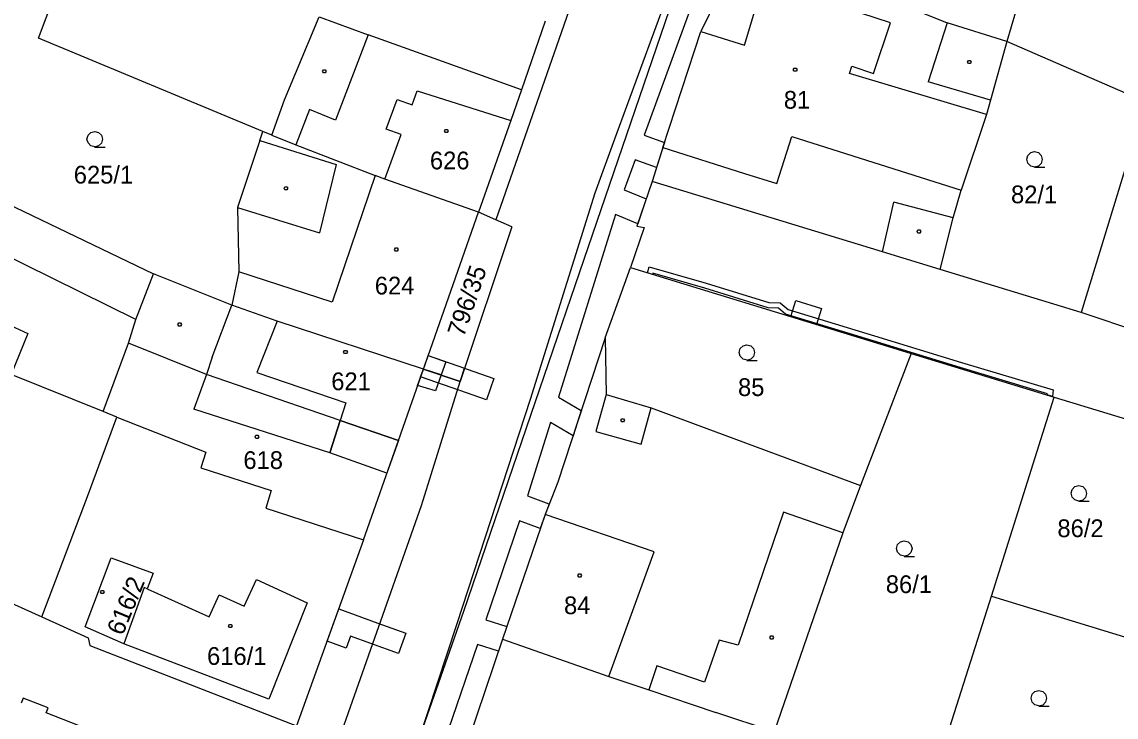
# Model space of a CAD drawing. Extents: x -759060 to -757386, y -1172273 to -1170948.
# Drawn here: x -758112.4 to -758007.6, y -1171497.5 to -1171430.9 of the extents above; entities that cross this region are included whole.
import ezdxf

# ---------------------------------------------------------------- set-up
doc = ezdxf.new("R2010")
doc.units = 0
for name, color, linetype in [('Vrstva 1', 7, 'Continuous'), ('Vrstva 12', 7, 'Continuous'), ('Vrstva 13', 7, 'Continuous'), ('Vrstva 2', 7, 'Continuous'), ('Vrstva 3', 7, 'Continuous'), ('Vrstva 4', 7, 'Continuous'), ('Vrstva 5', 7, 'Continuous')]:
    doc.layers.add(name, color=color, linetype=linetype)

msp = doc.modelspace()

# ---------------------------------------------------------------- linework, layer by layer
at = {"layer": 'Vrstva 1'}
for p, q in [((-758110.83, -1171432.43), (-758104.44, -1171415.39)), ((-758046.35, -1171417.81), (-758059.41, -1171456.07)), ((-758043.49, -1171423.81), (-758047.38, -1171431.8)), ((-758036.5, -1171425.83), (-758023.76, -1171430.96)), ((-758016.01, -1171425.87), (-758018.06, -1171432.75)), ((-758059.12, -1171427.2), (-758067.02, -1171449.84)), ((-758087.25, -1171438.35), (-758083.93, -1171430.4)), ((-758083.93, -1171430.4), (-758079.26, -1171432.11)), ((-758062.28, -1171430.8), (-758064.57, -1171437.39)), ((-758018.06, -1171432.75), (-758023.76, -1171430.96)), ((-758089.34, -1171441.38), (-758110.83, -1171432.43)), ((-758064.57, -1171437.39), (-758079.26, -1171432.11)), ((-758051.01, -1171442.93), (-758047.38, -1171431.8)), ((-758018.06, -1171432.75), (-758019.63, -1171438.39)), ((-758004.78, -1171438.56), (-758018.06, -1171432.75)), ((-758064.57, -1171437.39), (-758065.59, -1171440.32)), ((-758088.48, -1171441.74), (-758087.25, -1171438.35)), ((-758019.63, -1171438.39), (-758020.01, -1171439.77)), ((-758004.78, -1171438.56), (-758010.94, -1171458.73)), ((-758020.01, -1171439.77), (-758022.43, -1171447.01)), ((-758065.59, -1171440.32), (-758068.67, -1171449.1)), ((-758089.63, -1171442.25), (-758089.34, -1171441.38)), ((-758088.48, -1171441.74), (-758089.34, -1171441.38)), ((-758088.48, -1171441.74), (-758086.18, -1171442.66)), ((-758089.63, -1171442.25), (-758091.78, -1171448.65)), ((-758086.18, -1171442.66), (-758078.58, -1171445.61)), ((-758051.01, -1171442.93), (-758052.05, -1171446.17)), ((-758077.64, -1171445.94), (-758078.58, -1171445.61)), ((-758068.67, -1171449.1), (-758077.64, -1171445.94)), ((-758116.29, -1171447.1), (-758099.8, -1171455.02)), ((-758052.05, -1171446.17), (-758053.5, -1171450.45)), ((-758029.96, -1171452.92), (-758052.05, -1171446.17)), ((-758023.21, -1171449.66), (-758022.43, -1171447.01)), ((-758091.78, -1171448.65), (-758091.65, -1171454.84)), ((-758073.95, -1171464.14), (-758068.67, -1171449.1)), ((-758067.02, -1171449.84), (-758068.67, -1171449.1)), ((-758065.49, -1171450.52), (-758067.02, -1171449.84)), ((-758024.46, -1171454.6), (-758023.21, -1171449.66)), ((-758065.49, -1171450.52), (-758070.43, -1171465.33)), ((-758052.81, -1171450.57), (-758054.12, -1171454.42)), ((-758053.5, -1171450.45), (-758052.81, -1171450.57)), ((-758101.51, -1171459.4), (-758117.63, -1171451.45)), ((-758024.46, -1171454.6), (-758029.96, -1171452.92)), ((-758056.54, -1171461.15), (-758054.12, -1171454.42)), ((-758054.12, -1171454.42), (-758028.57, -1171462.23)), ((-758092.32, -1171458.03), (-758099.8, -1171455.02)), ((-758091.65, -1171454.84), (-758092.32, -1171458.03)), ((-758010.94, -1171458.73), (-758024.46, -1171454.6)), ((-758059.41, -1171456.07), (-758070.1, -1171487.39)), ((-758087.98, -1171459.55), (-758092.32, -1171458.03)), ((-757992.49, -1171464.9), (-758010.94, -1171458.73)), ((-758102.21, -1171461.65), (-758101.51, -1171459.4)), ((-758073.95, -1171464.14), (-758087.98, -1171459.55)), ((-758094.74, -1171464.66), (-758102.21, -1171461.65)), ((-758056.54, -1171461.15), (-758061.08, -1171474.99)), ((-758056.54, -1171461.15), (-758056.45, -1171466.59)), ((-758027.23, -1171462.64), (-758032.08, -1171475.31)), ((-758028.57, -1171462.23), (-758027.23, -1171462.64)), ((-758027.23, -1171462.64), (-758013.51, -1171466.83)), ((-758104.65, -1171468.2), (-758113.46, -1171464.68)), ((-758081.93, -1171469.06), (-758094.74, -1171464.66)), ((-758076.35, -1171470.98), (-758073.95, -1171464.14)), ((-758073.95, -1171464.14), (-758070.43, -1171465.33)), ((-758074.15, -1171477.21), (-758070.43, -1171465.33)), ((-758056.45, -1171466.59), (-758052.12, -1171467.85)), ((-758019.54, -1171485.89), (-758013.51, -1171466.83)), ((-758013.51, -1171466.83), (-757981.97, -1171476.47)), ((-758052.12, -1171467.85), (-758032.08, -1171475.31)), ((-758106.13, -1171476.36), (-758103.32, -1171468.77)), ((-758103.32, -1171468.77), (-758104.65, -1171468.2)), ((-758103.32, -1171468.77), (-758094.81, -1171472.1)), ((-758076.35, -1171470.98), (-758081.93, -1171469.06)), ((-758079.69, -1171480.51), (-758076.35, -1171470.98)), ((-758094.81, -1171472.1), (-758095.29, -1171473.61)), ((-758095.29, -1171473.61), (-758088.54, -1171475.77)), ((-758061.08, -1171474.99), (-758062.3, -1171478.07)), ((-758032.08, -1171475.31), (-758033.78, -1171479.83)), ((-758110.52, -1171487.88), (-758106.13, -1171476.36)), ((-758088.54, -1171475.77), (-758089.05, -1171477.46)), ((-758089.05, -1171477.46), (-758079.69, -1171480.51)), ((-758084.78, -1171507.41), (-758074.15, -1171477.21)), ((-758062.3, -1171478.07), (-758066.38, -1171490.03)), ((-758079.69, -1171480.51), (-758086.11, -1171498.34)), ((-758033.78, -1171479.83), (-758040.36, -1171498.92)), ((-758106.36, -1171488.85), (-758103.86, -1171482.22)), ((-758103.86, -1171482.22), (-758099.86, -1171483.71)), ((-758099.86, -1171483.71), (-758100.41, -1171485.2)), ((-758115.54, -1171485.61), (-758110.52, -1171487.88)), ((-758100.71, -1171485.09), (-758102.66, -1171490.46)), ((-758100.41, -1171485.2), (-758100.71, -1171485.09)), ((-758025.27, -1171504), (-758019.54, -1171485.89)), ((-758019.54, -1171485.89), (-757986.07, -1171496.14)), ((-758110.52, -1171487.88), (-758106.09, -1171489.91)), ((-758070.1, -1171487.39), (-758079.12, -1171512.99)), ((-758102.66, -1171490.46), (-758106.36, -1171488.85)), ((-758106.09, -1171489.91), (-758105.93, -1171490.64)), ((-758066.38, -1171490.03), (-758075.53, -1171517.08)), ((-758066.38, -1171490.03), (-758056.18, -1171493.59)), ((-758105.93, -1171490.64), (-758086.11, -1171498.34)), ((-758056.18, -1171493.59), (-758052.37, -1171494.89)), ((-758052.37, -1171494.89), (-758045.94, -1171497.05)), ((-758040.36, -1171498.92), (-758045.94, -1171497.05))]:
    msp.add_line(p, q, dxfattribs=at)
at = {"layer": 'Vrstva 12'}
for p, q in [((-758043.18, -1171433.12), (-758041.4, -1171427.09)), ((-758029.2, -1171430.96), (-758032.03, -1171430.06)), ((-758030.83, -1171435.82), (-758029.2, -1171430.96)), ((-758051.01, -1171442.93), (-758047.38, -1171431.8)), ((-758047.38, -1171431.8), (-758043.18, -1171433.12)), ((-758033.12, -1171435.84), (-758032.91, -1171435.12)), ((-758032.91, -1171435.12), (-758030.83, -1171435.82)), ((-758020.01, -1171439.77), (-758033.12, -1171435.84)), ((-758075.04, -1171438.83), (-758074.56, -1171437.5)), ((-758074.56, -1171437.5), (-758065.59, -1171440.32)), ((-758077.51, -1171441.16), (-758076.47, -1171438.31)), ((-758076.47, -1171438.31), (-758075.04, -1171438.83)), ((-758020.01, -1171439.77), (-758022.43, -1171447.01)), ((-758065.59, -1171440.32), (-758068.67, -1171449.1)), ((-758077.64, -1171445.94), (-758076.09, -1171441.68)), ((-758076.09, -1171441.68), (-758077.51, -1171441.16)), ((-758040.1, -1171446.38), (-758038.66, -1171441.86)), ((-758038.66, -1171441.86), (-758022.43, -1171447.01)), ((-758051.01, -1171442.93), (-758043.19, -1171445.4)), ((-758078.58, -1171445.61), (-758082.71, -1171457.73)), ((-758077.64, -1171445.94), (-758078.58, -1171445.61)), ((-758068.67, -1171449.1), (-758077.64, -1171445.94)), ((-758068.67, -1171449.1), (-758077.64, -1171445.94)), ((-758043.19, -1171445.4), (-758040.1, -1171446.38)), ((-758073.95, -1171464.14), (-758068.67, -1171449.1)), ((-758091.65, -1171454.84), (-758092.32, -1171458.03)), ((-758082.71, -1171457.73), (-758091.65, -1171454.84)), ((-758087.98, -1171459.55), (-758092.32, -1171458.03)), ((-758087.98, -1171459.55), (-758089.92, -1171464.48)), ((-758073.95, -1171464.14), (-758087.98, -1171459.55)), ((-758073.95, -1171464.14), (-758087.98, -1171459.55)), ((-758104.65, -1171468.2), (-758102.21, -1171461.65)), ((-758094.74, -1171464.66), (-758102.21, -1171461.65)), ((-758094.74, -1171464.66), (-758095.96, -1171467.98)), ((-758089.92, -1171464.48), (-758081.4, -1171467.39)), ((-758076.35, -1171470.98), (-758073.95, -1171464.14)), ((-758082.93, -1171472.16), (-758095.96, -1171467.98)), ((-758081.4, -1171467.39), (-758081.93, -1171469.06)), ((-758103.32, -1171468.77), (-758104.65, -1171468.2)), ((-758103.32, -1171468.77), (-758094.81, -1171472.1)), ((-758081.93, -1171469.06), (-758082.93, -1171472.16)), ((-758076.35, -1171470.98), (-758081.93, -1171469.06)), ((-758076.35, -1171470.98), (-758081.93, -1171469.06)), ((-758079.69, -1171480.51), (-758076.35, -1171470.98)), ((-758094.81, -1171472.1), (-758095.29, -1171473.61)), ((-758095.29, -1171473.61), (-758088.54, -1171475.77)), ((-758088.54, -1171475.77), (-758089.05, -1171477.46)), ((-758089.05, -1171477.46), (-758079.69, -1171480.51)), ((-758062.3, -1171478.07), (-758066.38, -1171490.03)), ((-758051.85, -1171481.65), (-758062.3, -1171478.07)), ((-758056.18, -1171493.59), (-758051.85, -1171481.65)), ((-758106.36, -1171488.85), (-758103.86, -1171482.22)), ((-758103.86, -1171482.22), (-758099.86, -1171483.71)), ((-758099.86, -1171483.71), (-758100.41, -1171485.2)), ((-758091.13, -1171486.88), (-758089.95, -1171484.32)), ((-758089.95, -1171484.32), (-758085.1, -1171486.56)), ((-758100.71, -1171485.09), (-758102.66, -1171490.46)), ((-758100.71, -1171485.09), (-758102.66, -1171490.46)), ((-758100.41, -1171485.2), (-758100.71, -1171485.09)), ((-758100.41, -1171485.2), (-758100.71, -1171485.09)), ((-758100.41, -1171485.2), (-758094.49, -1171487.89)), ((-758094.49, -1171487.89), (-758093.52, -1171485.78)), ((-758093.52, -1171485.78), (-758091.13, -1171486.88)), ((-758085.1, -1171486.56), (-758088.77, -1171495.79)), ((-758102.66, -1171490.46), (-758106.36, -1171488.85)), ((-758066.38, -1171490.03), (-758056.18, -1171493.59)), ((-758088.77, -1171495.79), (-758102.66, -1171490.46)), ((-758112.3, -1171495.68), (-758112.48, -1171496.15)), ((-758109.92, -1171496.61), (-758112.3, -1171495.68)), ((-758110.11, -1171497.08), (-758109.92, -1171496.61)), ((-758107, -1171498.3), (-758110.11, -1171497.08))]:
    msp.add_line(p, q, dxfattribs=at)
at = {"layer": 'Vrstva 13'}
for p, q in [((-758055.6, -1171442.07), (-758047.66, -1171420.43)), ((-758045.73, -1171422.42), (-758052.82, -1171441.75)), ((-758052.82, -1171441.75), (-758050.85, -1171442.45)), ((-758057.5, -1171447.26), (-758055.6, -1171442.07)), ((-758050.85, -1171442.45), (-758051.62, -1171444.83)), ((-758053.68, -1171444.09), (-758054.73, -1171446.97)), ((-758051.62, -1171444.83), (-758053.68, -1171444.09)), ((-758054.73, -1171446.97), (-758052.62, -1171447.84)), ((-758063.69, -1171467.03), (-758057.5, -1171447.26)), ((-758052.62, -1171447.84), (-758053.42, -1171450.22)), ((-758055.54, -1171449.34), (-758061.01, -1171466.83)), ((-758053.42, -1171450.22), (-758055.54, -1171449.34)), ((-758052.48, -1171454.92), (-758052.33, -1171454.34)), ((-758052.33, -1171454.34), (-758046.86, -1171455.91)), ((-758052, -1171455.07), (-758052.48, -1171454.92)), ((-758051.97, -1171454.96), (-758052, -1171455.07)), ((-758047, -1171456.39), (-758051.97, -1171454.96)), ((-758040.94, -1171458.28), (-758047, -1171456.39)), ((-758046.86, -1171455.91), (-758040.86, -1171457.78)), ((-758038.74, -1171459.12), (-758038.27, -1171457.58)), ((-758038.27, -1171457.58), (-758035.82, -1171458.33)), ((-758039.94, -1171458.31), (-758040.94, -1171458.28)), ((-758040.86, -1171457.78), (-758039.76, -1171457.81)), ((-758039.26, -1171458.88), (-758039.94, -1171458.31)), ((-758039.76, -1171457.81), (-758039.02, -1171458.44)), ((-758039.02, -1171458.44), (-758030.74, -1171460.96)), ((-758035.82, -1171458.33), (-758036.29, -1171459.87)), ((-758030.88, -1171461.44), (-758039.26, -1171458.88)), ((-758036.29, -1171459.87), (-758038.74, -1171459.12)), ((-758022.53, -1171464), (-758030.88, -1171461.44)), ((-758030.74, -1171460.96), (-758022.39, -1171463.52)), ((-758073.95, -1171464.14), (-758073.5, -1171462.85)), ((-758073.95, -1171464.14), (-758073.5, -1171462.85)), ((-758073.5, -1171462.85), (-758070.01, -1171464.07)), ((-758073.5, -1171462.85), (-758071.8, -1171463.44)), ((-758071.8, -1171463.44), (-758072.26, -1171464.71)), ((-758022.39, -1171463.52), (-758013.62, -1171466.15)), ((-758074.51, -1171465.73), (-758073.95, -1171464.14)), ((-758074.22, -1171464.9), (-758073.95, -1171464.14)), ((-758070.46, -1171466.21), (-758074.22, -1171464.9)), ((-758070.43, -1171465.33), (-758073.95, -1171464.14)), ((-758073.95, -1171464.14), (-758070.43, -1171465.33)), ((-758072.26, -1171464.71), (-758073.95, -1171464.14)), ((-758073.95, -1171464.14), (-758072.26, -1171464.71)), ((-758072.26, -1171464.71), (-758072.8, -1171466.24)), ((-758070.01, -1171464.07), (-758070.43, -1171465.33)), ((-758070.43, -1171465.33), (-758070.01, -1171464.07)), ((-758070.01, -1171464.07), (-758069.75, -1171464.17)), ((-758069.75, -1171464.17), (-758067.2, -1171465.06)), ((-758014.16, -1171466.51), (-758022.53, -1171464)), ((-758072.8, -1171466.24), (-758074.51, -1171465.73)), ((-758067.2, -1171465.06), (-758067.92, -1171467.1)), ((-758070.73, -1171488.51), (-758063.69, -1171467.03)), ((-758067.92, -1171467.1), (-758070.46, -1171466.21)), ((-758061.01, -1171466.83), (-758058.83, -1171468.12)), ((-758014.18, -1171466.63), (-758014.16, -1171466.51)), ((-758013.69, -1171466.78), (-758014.18, -1171466.63)), ((-758013.62, -1171466.15), (-758013.69, -1171466.78)), ((-758058.83, -1171468.12), (-758059.62, -1171470.55)), ((-758082.93, -1171472.16), (-758081.93, -1171469.06)), ((-758081.93, -1171469.06), (-758076.35, -1171470.98)), ((-758061.78, -1171469.28), (-758063.97, -1171476.3)), ((-758059.62, -1171470.55), (-758061.78, -1171469.28)), ((-758076.35, -1171470.98), (-758077.45, -1171474.12)), ((-758077.45, -1171474.12), (-758082.93, -1171472.16)), ((-758063.97, -1171476.3), (-758061.94, -1171477.07)), ((-758061.91, -1171477.08), (-758062.3, -1171478.07)), ((-758061.94, -1171477.07), (-758061.91, -1171477.08)), ((-758062.3, -1171478.07), (-758062.76, -1171479.43)), ((-758064.75, -1171478.68), (-758067.97, -1171488.16)), ((-758062.76, -1171479.43), (-758064.75, -1171478.68)), ((-758083.19, -1171490.22), (-758082.07, -1171487.13)), ((-758082.07, -1171487.13), (-758078.31, -1171488.48)), ((-758084.83, -1171531.29), (-758070.73, -1171488.51)), ((-758078.31, -1171488.48), (-758075.65, -1171489.44)), ((-758067.97, -1171488.16), (-758065.95, -1171488.82)), ((-758065.95, -1171488.82), (-758066.38, -1171490.03)), ((-758080.94, -1171489.73), (-758081.35, -1171490.88)), ((-758079, -1171490.43), (-758080.94, -1171489.73)), ((-758075.65, -1171489.44), (-758076.35, -1171491.39)), ((-758066.38, -1171490.03), (-758066.75, -1171491.18)), ((-758081.35, -1171490.88), (-758083.19, -1171490.22)), ((-758076.35, -1171491.39), (-758079, -1171490.43)), ((-758068.78, -1171490.53), (-758072.87, -1171502.5)), ((-758066.75, -1171491.18), (-758068.78, -1171490.53))]:
    msp.add_line(p, q, dxfattribs=at)
at = {"layer": 'Vrstva 3'}
for points in [[(-758105.44, -1171442.85), (-758105.82, -1171442.75), (-758106.09, -1171442.48), (-758106.19, -1171442.11), (-758106.09, -1171441.74), (-758105.82, -1171441.47), (-758105.45, -1171441.37), (-758105.08, -1171441.47), (-758104.81, -1171441.74), (-758104.71, -1171442.12), (-758104.81, -1171442.5), (-758105.08, -1171442.77), (-758105.46, -1171442.87), (-758104.46, -1171442.87)], [(-758015.39, -1171444.79), (-758015.77, -1171444.69), (-758016.04, -1171444.42), (-758016.14, -1171444.05), (-758016.04, -1171443.68), (-758015.77, -1171443.41), (-758015.4, -1171443.31), (-758015.03, -1171443.41), (-758014.76, -1171443.68), (-758014.66, -1171444.06), (-758014.76, -1171444.44), (-758015.03, -1171444.71), (-758015.41, -1171444.81), (-758014.41, -1171444.81)], [(-758042.95, -1171463.29), (-758043.33, -1171463.19), (-758043.6, -1171462.92), (-758043.7, -1171462.55), (-758043.6, -1171462.18), (-758043.33, -1171461.91), (-758042.96, -1171461.81), (-758042.59, -1171461.91), (-758042.32, -1171462.18), (-758042.22, -1171462.56), (-758042.32, -1171462.94), (-758042.59, -1171463.21), (-758042.97, -1171463.31), (-758041.97, -1171463.31)], [(-758011.15, -1171476.79), (-758011.53, -1171476.69), (-758011.8, -1171476.42), (-758011.9, -1171476.05), (-758011.8, -1171475.68), (-758011.53, -1171475.41), (-758011.16, -1171475.31), (-758010.79, -1171475.41), (-758010.52, -1171475.68), (-758010.42, -1171476.06), (-758010.52, -1171476.44), (-758010.79, -1171476.71), (-758011.17, -1171476.81), (-758010.17, -1171476.81)], [(-758027.87, -1171482.07), (-758028.25, -1171481.97), (-758028.52, -1171481.7), (-758028.62, -1171481.33), (-758028.52, -1171480.96), (-758028.25, -1171480.69), (-758027.88, -1171480.59), (-758027.51, -1171480.69), (-758027.24, -1171480.96), (-758027.14, -1171481.34), (-758027.24, -1171481.72), (-758027.51, -1171481.99), (-758027.89, -1171482.09), (-758026.89, -1171482.09)], [(-758014.98, -1171496.42), (-758015.36, -1171496.32), (-758015.63, -1171496.05), (-758015.73, -1171495.68), (-758015.63, -1171495.31), (-758015.36, -1171495.04), (-758014.99, -1171494.94), (-758014.62, -1171495.04), (-758014.35, -1171495.31), (-758014.25, -1171495.69), (-758014.35, -1171496.07), (-758014.62, -1171496.34), (-758015, -1171496.44), (-758014, -1171496.44)]]:
    msp.add_lwpolyline(points, dxfattribs=at)
at = {"layer": 'Vrstva 4'}
for p, q in [((-758043.18, -1171433.12), (-758041.4, -1171427.09)), ((-758029.2, -1171430.96), (-758032.03, -1171430.06)), ((-758030.83, -1171435.82), (-758029.2, -1171430.96)), ((-758023.76, -1171430.96), (-758025.61, -1171436.63)), ((-758079.26, -1171432.11), (-758082.38, -1171440.29)), ((-758047.38, -1171431.8), (-758043.18, -1171433.12)), ((-758033.12, -1171435.84), (-758032.91, -1171435.12)), ((-758032.91, -1171435.12), (-758030.83, -1171435.82)), ((-758020.01, -1171439.77), (-758033.12, -1171435.84)), ((-758019.63, -1171438.39), (-758025.61, -1171436.63)), ((-758075.04, -1171438.83), (-758074.56, -1171437.5)), ((-758074.56, -1171437.5), (-758065.59, -1171440.32)), ((-758077.51, -1171441.16), (-758076.47, -1171438.31)), ((-758076.47, -1171438.31), (-758075.04, -1171438.83)), ((-758084.88, -1171439.28), (-758086.18, -1171442.66)), ((-758082.38, -1171440.29), (-758084.88, -1171439.28)), ((-758077.64, -1171445.94), (-758076.09, -1171441.68)), ((-758076.09, -1171441.68), (-758077.51, -1171441.16)), ((-758040.1, -1171446.38), (-758038.66, -1171441.86)), ((-758038.66, -1171441.86), (-758022.43, -1171447.01)), ((-758089.63, -1171442.25), (-758082.31, -1171444.54)), ((-758051.01, -1171442.93), (-758043.19, -1171445.4)), ((-758082.31, -1171444.54), (-758083.91, -1171451.09)), ((-758078.58, -1171445.61), (-758082.71, -1171457.73)), ((-758043.19, -1171445.4), (-758040.1, -1171446.38)), ((-758029.96, -1171452.92), (-758028.89, -1171448.14)), ((-758023.21, -1171449.66), (-758028.89, -1171448.14)), ((-758091.78, -1171448.65), (-758083.91, -1171451.09)), ((-758101.51, -1171459.4), (-758099.8, -1171455.02)), ((-758082.71, -1171457.73), (-758091.65, -1171454.84)), ((-758094.18, -1171463.02), (-758092.32, -1171458.03)), ((-758115.53, -1171459.03), (-758111.86, -1171460.75)), ((-758087.98, -1171459.55), (-758089.92, -1171464.48)), ((-758111.86, -1171460.75), (-758113.46, -1171464.68)), ((-758104.65, -1171468.2), (-758102.21, -1171461.65)), ((-758094.18, -1171463.02), (-758094.74, -1171464.66)), ((-758094.74, -1171464.66), (-758095.96, -1171467.98)), ((-758089.92, -1171464.48), (-758081.4, -1171467.39)), ((-758056.45, -1171466.59), (-758057.45, -1171470.13)), ((-758082.93, -1171472.16), (-758095.96, -1171467.98)), ((-758081.4, -1171467.39), (-758081.93, -1171469.06)), ((-758053.09, -1171471.35), (-758052.12, -1171467.85)), ((-758081.93, -1171469.06), (-758082.93, -1171472.16)), ((-758057.45, -1171470.13), (-758053.09, -1171471.35)), ((-758051.85, -1171481.65), (-758062.3, -1171478.07)), ((-758039.45, -1171477.87), (-758043.79, -1171490.61)), ((-758033.78, -1171479.83), (-758039.45, -1171477.87)), ((-758056.18, -1171493.59), (-758051.85, -1171481.65)), ((-758091.13, -1171486.88), (-758089.95, -1171484.32)), ((-758089.95, -1171484.32), (-758085.1, -1171486.56)), ((-758100.41, -1171485.2), (-758094.49, -1171487.89)), ((-758094.49, -1171487.89), (-758093.52, -1171485.78)), ((-758093.52, -1171485.78), (-758091.13, -1171486.88)), ((-758085.1, -1171486.56), (-758088.77, -1171495.79)), ((-758045.63, -1171490.13), (-758047.02, -1171494.14)), ((-758043.79, -1171490.61), (-758045.63, -1171490.13)), ((-758088.77, -1171495.79), (-758102.66, -1171490.46)), ((-758051.58, -1171492.58), (-758052.37, -1171494.89)), ((-758047.02, -1171494.14), (-758051.58, -1171492.58)), ((-758112.3, -1171495.68), (-758112.48, -1171496.15)), ((-758109.92, -1171496.61), (-758112.3, -1171495.68)), ((-758110.11, -1171497.08), (-758109.92, -1171496.61)), ((-758107, -1171498.3), (-758110.11, -1171497.08))]:
    msp.add_line(p, q, dxfattribs=at)
at = {"layer": 'Vrstva 5'}
for points in [[(-758021.56, -1171434.58), (-758021.47, -1171434.73), (-758021.56, -1171434.88), (-758021.74, -1171434.88), (-758021.83, -1171434.73), (-758021.74, -1171434.58)], [(-758083.36, -1171435.46), (-758083.27, -1171435.61), (-758083.36, -1171435.76), (-758083.54, -1171435.76), (-758083.63, -1171435.61), (-758083.54, -1171435.46)], [(-758038.25, -1171435.31), (-758038.16, -1171435.46), (-758038.25, -1171435.61), (-758038.43, -1171435.61), (-758038.52, -1171435.46), (-758038.43, -1171435.31)], [(-758071.67, -1171441.18), (-758071.58, -1171441.33), (-758071.67, -1171441.48), (-758071.85, -1171441.48), (-758071.94, -1171441.33), (-758071.85, -1171441.18)], [(-758087.04, -1171446.67), (-758086.95, -1171446.82), (-758087.04, -1171446.97), (-758087.22, -1171446.97), (-758087.31, -1171446.82), (-758087.22, -1171446.67)], [(-758026.39, -1171450.82), (-758026.3, -1171450.97), (-758026.39, -1171451.12), (-758026.57, -1171451.12), (-758026.66, -1171450.97), (-758026.57, -1171450.82)], [(-758076.46, -1171452.54), (-758076.37, -1171452.69), (-758076.46, -1171452.84), (-758076.64, -1171452.84), (-758076.73, -1171452.69), (-758076.64, -1171452.54)], [(-758097.22, -1171459.73), (-758097.13, -1171459.88), (-758097.22, -1171460.03), (-758097.4, -1171460.03), (-758097.49, -1171459.88), (-758097.4, -1171459.73)], [(-758081.33, -1171462.37), (-758081.24, -1171462.52), (-758081.33, -1171462.67), (-758081.51, -1171462.67), (-758081.6, -1171462.52), (-758081.51, -1171462.37)], [(-758054.77, -1171468.9), (-758054.68, -1171469.05), (-758054.77, -1171469.2), (-758054.95, -1171469.2), (-758055.04, -1171469.05), (-758054.95, -1171468.9)], [(-758089.82, -1171470.49), (-758089.73, -1171470.64), (-758089.82, -1171470.79), (-758090, -1171470.79), (-758090.09, -1171470.64), (-758090, -1171470.49)], [(-758058.9, -1171483.78), (-758058.81, -1171483.93), (-758058.9, -1171484.08), (-758059.08, -1171484.08), (-758059.17, -1171483.93), (-758059.08, -1171483.78)], [(-758104.63, -1171485.35), (-758104.54, -1171485.5), (-758104.63, -1171485.65), (-758104.81, -1171485.65), (-758104.9, -1171485.5), (-758104.81, -1171485.35)], [(-758092.36, -1171488.61), (-758092.27, -1171488.76), (-758092.36, -1171488.91), (-758092.54, -1171488.91), (-758092.63, -1171488.76), (-758092.54, -1171488.61)], [(-758040.5, -1171489.72), (-758040.41, -1171489.87), (-758040.5, -1171490.02), (-758040.68, -1171490.02), (-758040.77, -1171489.87), (-758040.68, -1171489.72)]]:
    msp.add_lwpolyline(points, close=True, dxfattribs=at)

# ---------------------------------------------------------------- texts
at = {"layer": 'Vrstva 2'}
for s, p in [('81', (-758039.424, -1171439.2)), ('626', (-758073.333, -1171445.01)), ('625/1', (-758107.453, -1171446.37)), ('82/1', (-758017.656, -1171448.26)), ('624', (-758078.613, -1171457)), ('621', (-758082.783, -1171466.17)), ('85', (-758043.813, -1171466.73)), ('618', (-758091.203, -1171473.72)), ('86/2', (-758013.213, -1171480.25)), ('86/1', (-758029.653, -1171485.61)), ('84', (-758060.483, -1171487.63)), ('616/1', (-758094.683, -1171492.49))]:
    msp.add_text(s, height=1.7, dxfattribs=at).set_placement(p)
for s, rotation, p in [('796/35', 71.27595, (-758070.094, -1171461.165)), ('616/2', 67.60902, (-758102.773, -1171489.761))]:
    msp.add_text(s, height=1.7, rotation=rotation, dxfattribs=at).set_placement(p)

doc.saveas('drawing.dxf')
